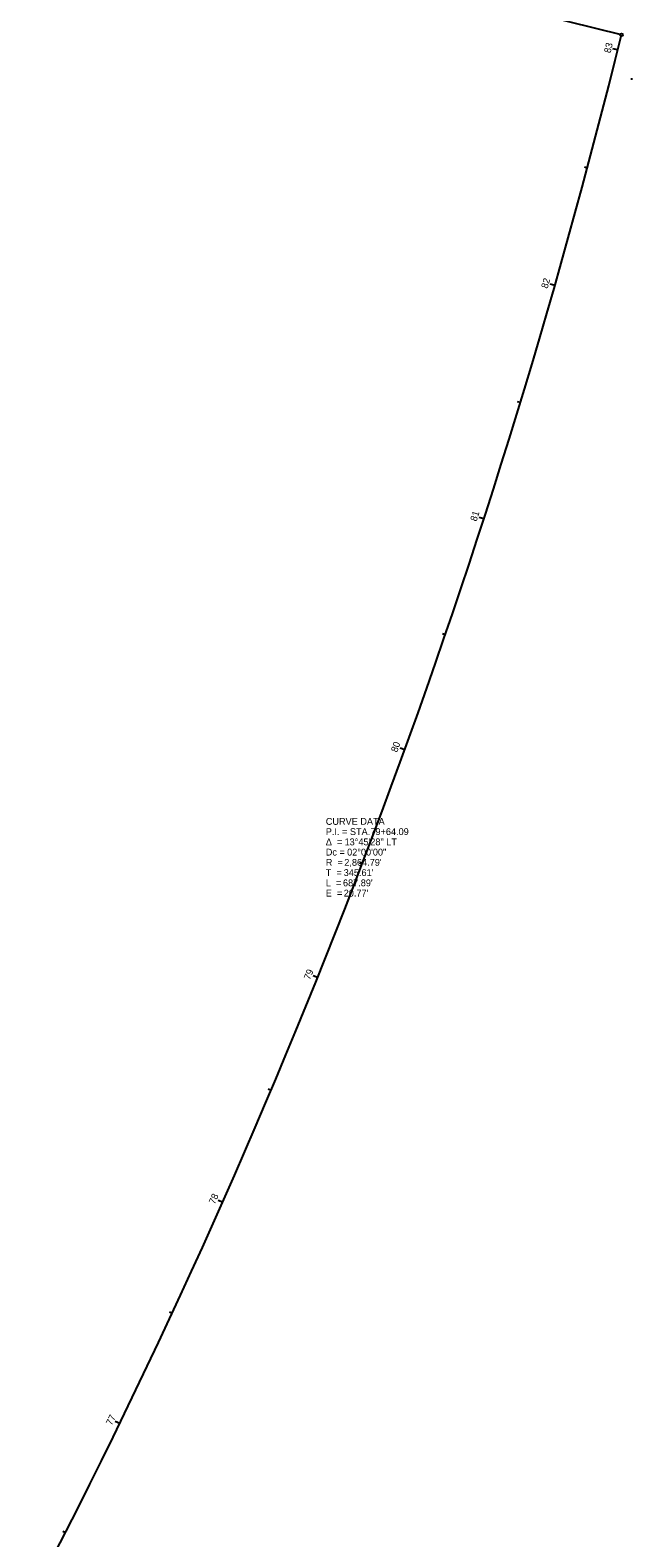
# Model space of a CAD drawing. Extents: x 2199669 to 2203518, y 635127 to 637305.
# Drawn here: x 2203085 to 2203331, y 635831 to 636449 of the extents above; entities that cross this region are included whole.
import ezdxf

# ---------------------------------------------------------------- set-up
doc = ezdxf.new("R2010")
doc.units = 0
for name, color, linetype in [('DT_X_Spot_Elev', 7, 'Continuous'), ('RD_P_GR_Lt', 7, 'Continuous'), ('RD_P_GR_Rt', 7, 'Continuous'), ('SC_Scratch1', 7, 'Continuous'), ('SC_Scratch2', 7, 'Continuous')]:
    doc.layers.add(name, color=color, linetype=linetype)

msp = doc.modelspace()

# ---------------------------------------------------------------- linework, layer by layer
at = {"layer": 'DT_X_Spot_Elev'}
msp.add_circle((2203331.27, 636429.38), 0.05, dxfattribs=at)
msp.add_circle((2203331.27, 636429.38), 0.05, dxfattribs=at)
msp.add_circle((2203331.27, 636429.38), 0.05, dxfattribs=at)
at = {"layer": 'RD_P_GR_Lt'}
msp.add_line((2203327.04, 636447.47), (2203283.34, 636458.2), dxfattribs=at)
msp.add_circle((2203327.04, 636447.47), 0.6, dxfattribs=at)
msp.add_circle((2203327.04, 636447.47), 0.6, dxfattribs=at)
at = {"layer": 'RD_P_GR_Rt'}
msp.add_arc((2200544.78, 637130.12), 2864.79, 332.45655, 346.21433, dxfattribs=at)
msp.add_arc((2200544.78, 637130.12), 2864.79, 332.45655, 346.21433, dxfattribs=at)
at = {"layer": 'SC_Scratch1'}
for p, q in [((2203325.52, 636441.29), (2203323.58, 636441.77)), ((2203313.07, 636392.86), (2203311.91, 636393.17)), ((2203299.79, 636344.66), (2203297.86, 636345.21)), ((2203285.66, 636296.7), (2203284.51, 636297.05)), ((2203270.69, 636248.99), (2203268.79, 636249.6)), ((2203254.9, 636201.55), (2203253.77, 636201.94)), ((2203238.28, 636154.39), (2203236.4, 636155.07)), ((2203220.84, 636107.53), (2203219.72, 636107.96)), ((2203202.59, 636060.99), (2203200.73, 636061.73)), ((2203183.53, 636014.76), (2203182.42, 636015.23)), ((2203163.66, 635968.88), (2203161.83, 635969.69)), ((2203142.99, 635923.35), (2203141.9, 635923.86)), ((2203121.54, 635878.19), (2203119.74, 635879.06)), ((2203099.29, 635833.41), (2203098.22, 635833.95))]:
    msp.add_line(p, q, dxfattribs=at)

# ---------------------------------------------------------------- texts
for s, rotation, p in [('83', 76.08689, (2203322.57, 636439.8)), ('82', 74.08689, (2203296.79, 636343.26)), ('81', 72.08689, (2203267.69, 636247.82)), ('80', 70.08689, (2203235.17, 636153.15)), ('79', 68.08689, (2203199.45, 636059.88)), ('78', 66.08689, (2203160.47, 635967.87)), ('77', 64.08689, (2203118.28, 635877.21))]:
    msp.add_text(s, height=2.8, rotation=rotation, dxfattribs=at).set_placement(p)
at = {"layer": 'SC_Scratch2'}
for s, p in [('CURVE DATA', (2203205.96, 636123.63)), ('P.I. = STA. ', (2203205.96, 636119.43)), ('79+64.09', (2203224.23, 636119.43)), ('Δ  = ', (2203205.96, 636115.23)), ('13°45\'28" LT', (2203213.64, 636115.23)), ('Dc = ', (2203205.96, 636111.03)), ('R  = ', (2203205.96, 636106.83)), ("2,864.79'", (2203213.54, 636106.83)), ('02°00\'00"', (2203214.7, 636111.03)), ('T  = ', (2203205.96, 636102.63)), ("345.61'", (2203213.3, 636102.63)), ('L  = ', (2203205.96, 636098.43)), ('E  = ', (2203205.96, 636094.23)), ("687.89'", (2203213, 636098.43)), ("20.77'", (2203213.3, 636094.23))]:
    msp.add_text(s, height=2.8, dxfattribs=at).set_placement(p)

doc.saveas('drawing.dxf')
